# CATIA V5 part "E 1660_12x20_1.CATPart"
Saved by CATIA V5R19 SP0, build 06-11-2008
Part number: E 1660_12x20_1
Definition: E 1660_12x20_1
Nomenclature: E 1660_12x20_1
Source: Unknown
Description: PART-E 1660_12x20_1-DESC
Bounding box of the stored display mesh (mm): x -8 to 8, y -8 to 8, z -20 to 0
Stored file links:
  C:\Users\jsmid\Desktop\DP_Smidak_Forma LEGO\E 1660_12x20_1.CATPart
  C:\Users\jsmid\Desktop\Forma_kostka\Babyplast_univ_ram_plus_LEGO_2.CATProduct
  C:\Users\jsmid\Desktop\Forma_kostka\vtok_2.CATPart
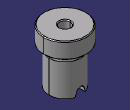
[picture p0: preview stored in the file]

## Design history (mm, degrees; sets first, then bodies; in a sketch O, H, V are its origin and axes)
Body1 "E 1660_12x20" (main body)
  Solid1: solid without history
  Plane1: stored without definition
  Plane2: stored without definition
  DatumCurve1 to DatumCurve5
  Sketch1 on Plane2, origin (0, 0, 0), H (-1, 0, 0), V (0, 0, 1)
    projected line E1 (-1.8927, -20) -> (1.9073, -20) from edge of DatumCurve2
    projected line E2 (1.9073, -20) -> (1.4562, -18.3164) from edge of DatumCurve3
    projected arc E3 centre (0.0073, -18.7048) radius 1.5 from (1.4562, -18.3164) to (-1.4415, -18.3164) ccw from edge of DatumCurve4
    projected line E4 (-1.4415, -18.3164) -> (-1.8926, -20) from edge of DatumCurve5
  Pocket1: profile Sketch1, direction (0, 1, 0), length 6, mirrored extent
